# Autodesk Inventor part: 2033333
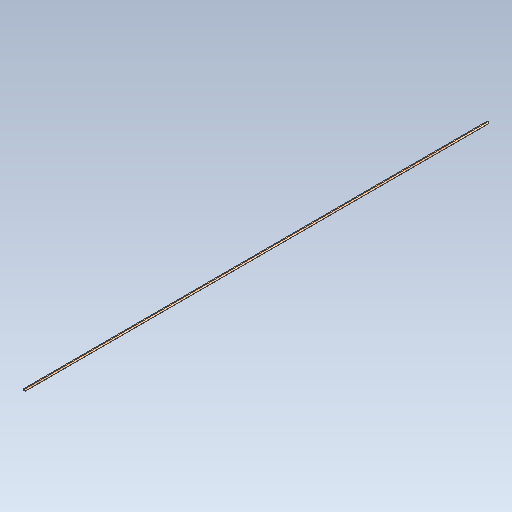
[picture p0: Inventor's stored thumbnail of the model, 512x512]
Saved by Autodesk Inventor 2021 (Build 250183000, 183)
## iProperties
Created: 2021-07
Part Number: 2033333
Material: Wood (Birch)
Document SubType Name: Sheet Metal
Designer: user
Density: 0.55 g/cm^3
Sheet Metal Rule: Default_mm
Appearance: Birch - Natural Polished
Author: user
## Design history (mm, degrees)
sketch "Sketch2"
  geometry: L1 (-1.769, 8.497)-(-1.569, 8.497); L2 (-1.569, 8.497)-(-1.423, 8.23); L3 (-1.423, 8.23)-(-1.422, 8.194); L4 (-1.422, 8.194)-(-1.885, 8.212); L5 (-1.885, 8.212)-(-1.883, 8.259); L6 (-1.883, 8.259)-(-1.769, 8.497); 1 further point
  constraints: 12 end point, 1 horizontal, 1 perpendicular
  dimensions: "d3" = 0.2 distance of L1.start L1.end; "d4" = 0.304 distance of L1.end L2.end
extrude "Extrusion2" new body sketch "Sketch2" distance "d5" = 100; taper "d6" = 0 deg
body "Solid2"
other parameters: "Thickness" = 0.5, "BendRadius" = 0.5 (= Thickness), "BendReliefWidth" = 0.5 (= Thickness), "BendReliefDepth" = 0.25 (= 0.5 x Thickness), "CornerReliefSize" = 2 (= 4 x Thickness), "SeamGap" = 0.01, "MinimumRemnant" = 1 (= 2 x Thickness), "TransitionRadius" = 0.5 (= BendRadius), "JacobiRadiusSize" = 0.5 (= BendRadius), "GapSize" = 0.5 (= Thickness)
